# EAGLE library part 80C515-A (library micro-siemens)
MICROPROCESSOR/PERIPHERAL DEVICE
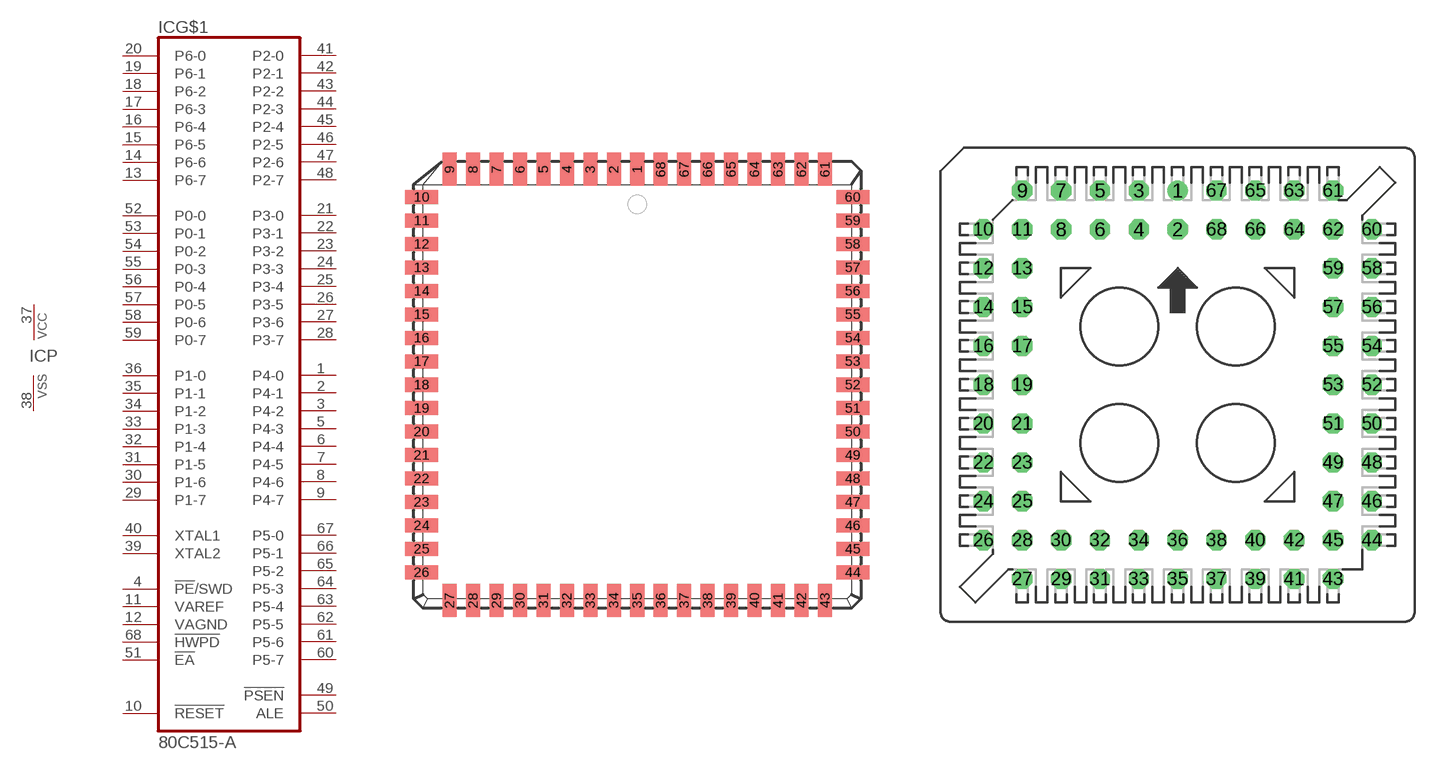
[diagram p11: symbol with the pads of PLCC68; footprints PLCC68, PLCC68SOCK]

Designator prefix IC; gates G$1=80C515-A P=VCCVSS

## 80C515-A (OC_FARNELL: unknown; OC_NEWARK: unknown)  [PLCC68]
1  G$1:P4-0
2  G$1:P4-1
3  G$1:P4-2
4  G$1:!PE!/SWD  in
5  G$1:P4-3
6  G$1:P4-4
7  G$1:P4-5
8  G$1:P4-6
9  G$1:P4-7
10  G$1:!RESET  in
11  G$1:VAREF  in
12  G$1:VAGND  in
13  G$1:P6-7  in
14  G$1:P6-6  in
15  G$1:P6-5  in
16  G$1:P6-4  in
17  G$1:P6-3  in
18  G$1:P6-2  in
19  G$1:P6-1  in
20  G$1:P6-0  in
21  G$1:P3-0
22  G$1:P3-1
23  G$1:P3-2
24  G$1:P3-3
25  G$1:P3-4
26  G$1:P3-5
27  G$1:P3-6
28  G$1:P3-7
29  G$1:P1-7
30  G$1:P1-6
31  G$1:P1-5
32  G$1:P1-4
33  G$1:P1-3
34  G$1:P1-2
35  G$1:P1-1
36  G$1:P1-0
37  P:VCC  pwr
38  P:VSS  pwr
39  G$1:XTAL2  pas
40  G$1:XTAL1  pas
41  G$1:P2-0
42  G$1:P2-1
43  G$1:P2-2
44  G$1:P2-3
45  G$1:P2-4
46  G$1:P2-5
47  G$1:P2-6
48  G$1:P2-7
49  G$1:!PSEN  out
50  G$1:ALE  out
51  G$1:!EA  in
52  G$1:P0-0
53  G$1:P0-1
54  G$1:P0-2
55  G$1:P0-3
56  G$1:P0-4
57  G$1:P0-5
58  G$1:P0-6
59  G$1:P0-7
60  G$1:P5-7
61  G$1:P5-6
62  G$1:P5-5
63  G$1:P5-4
64  G$1:P5-3
65  G$1:P5-2
66  G$1:P5-1
67  G$1:P5-0
68  G$1:!HWPD  pas

## 80C515-ASOCK (OC_FARNELL: unknown; OC_NEWARK: unknown)  [PLCC68SOCK]
Pads as for PLCC68

## Footprint PLCC68 (pad centres in mm)
PLASTIC LEADED CHIP CARRIER square
smd 0.76 x 1.8: 1 0,11.67; 2 -1.27,11.67; 3 -2.54,11.67; 4 -3.81,11.67; 5 -5.08,11.67; 6 -6.35,11.67; 7 -7.62,11.67; 8 -8.89,11.67; 9 -10.16,11.67; 27 -10.16,-11.67; 28 -8.89,-11.67; 29 -7.62,-11.67; 30 -6.35,-11.67; 31 -5.08,-11.67; 32 -3.81,-11.67; 33 -2.54,-11.67; 34 -1.27,-11.67; 35 0,-11.67; 36 1.27,-11.67; 37 2.54,-11.67; 38 3.81,-11.67; 39 5.08,-11.67; 40 6.35,-11.67; 41 7.62,-11.67; 42 8.89,-11.67; 43 10.16,-11.67; 61 10.16,11.67; 62 8.89,11.67; 63 7.62,11.67; 64 6.35,11.67; 65 5.08,11.67; 66 3.81,11.67; 67 2.54,11.67; 68 1.27,11.67
smd 1.8 x 0.76: 10 -11.67,10.16; 11 -11.67,8.89; 12 -11.67,7.62; 13 -11.67,6.35; 14 -11.67,5.08; 15 -11.67,3.81; 16 -11.67,2.54; 17 -11.67,1.27; 18 -11.67,0; 19 -11.67,-1.27; 20 -11.67,-2.54; 21 -11.67,-3.81; 22 -11.67,-5.08; 23 -11.67,-6.35; 24 -11.67,-7.62; 25 -11.67,-8.89; 26 -11.67,-10.16; 44 11.67,-10.16; 45 11.67,-8.89; 46 11.67,-7.62; 47 11.67,-6.35; 48 11.67,-5.08; 49 11.67,-3.81; 50 11.67,-2.54; 51 11.67,-1.27; 52 11.67,0; 53 11.67,1.27; 54 11.67,2.54; 55 11.67,3.81; 56 11.67,5.08; 57 11.67,6.35; 58 11.67,7.62; 59 11.67,8.89; 60 11.67,10.16

## Footprint PLCC68SOCK (pad centres in mm)
PLASTIC LEADED CHIP CARRIER socked
drill 0.813 round: 1 0,12.7
drill 0.813 octagon: 2 0,10.16; 3 -2.54,12.7; 4 -2.54,10.16; 5 -5.08,12.7; 6 -5.08,10.16; 7 -7.62,12.7; 8 -7.62,10.16; 9 -10.16,12.7; 10 -12.7,10.16; 11 -10.16,10.16; 12 -12.7,7.62; 13 -10.16,7.62; 14 -12.7,5.08; 15 -10.16,5.08; 16 -12.7,2.54; 17 -10.16,2.54; 18 -12.7,0; 19 -10.16,0; 20 -12.7,-2.54; 21 -10.16,-2.54; 22 -12.7,-5.08; 23 -10.16,-5.08; 24 -12.7,-7.62; 25 -10.16,-7.62; 26 -12.7,-10.16; 27 -10.16,-12.7; 28 -10.16,-10.16; 29 -7.62,-12.7; 30 -7.62,-10.16; 31 -5.08,-12.7; 32 -5.08,-10.16; 33 -2.54,-12.7; 34 -2.54,-10.16; 35 0,-12.7; 36 0,-10.16; 37 2.54,-12.7; 38 2.54,-10.16; 39 5.08,-12.7; 40 5.08,-10.16; 41 7.62,-12.7; 42 7.62,-10.16; 43 10.16,-12.7; 44 12.7,-10.16; 45 10.16,-10.16; 46 12.7,-7.62; 47 10.16,-7.62; 48 12.7,-5.08; 49 10.16,-5.08; 50 12.7,-2.54; 51 10.16,-2.54; 52 12.7,0; 53 10.16,0; 54 12.7,2.54; 55 10.16,2.54; 56 12.7,5.08; 57 10.16,5.08; 58 12.7,7.62; 59 10.16,7.62; 60 12.7,10.16; 61 10.16,12.7; 62 10.16,10.16; 63 7.62,12.7; 64 7.62,10.16; 65 5.08,12.7; 66 5.08,10.16; 67 2.54,12.7; 68 2.54,10.16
